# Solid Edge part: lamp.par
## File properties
Author: Romil
Template: Iso Part.par
Last saved by: Romil
Revision: 5
Application: Solid Edge
Accuracy: 0.990
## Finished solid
Body 1: solid body, 13 faces, 13 edges, 0 vertices.
  Faces by surface: plane 6, cylinder 5, torus 2
  Edges by curve: circle 13
Bounding box of the edges (mm; curved faces can reach further): 15.500 x 15.500 x 5.000, from (-7.75, -7.75, 0) to (7.75, 7.75, 5).
Cylindrical faces by radius (mm): R1.25 x1, R2 x1, R2.4 x2, R3.1 x1
Toroidal faces (ring radius, tube radius in mm): R2.5538 r5.6 x1, R2.5538 r6 x1
Planar faces by outward normal: +z 2, -z 4
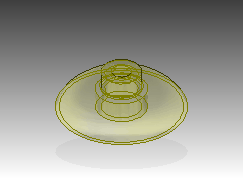
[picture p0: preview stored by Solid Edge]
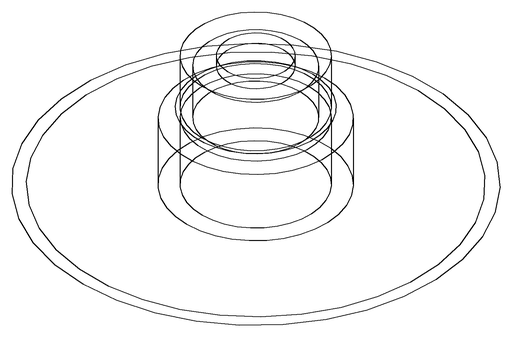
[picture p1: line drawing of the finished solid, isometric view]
